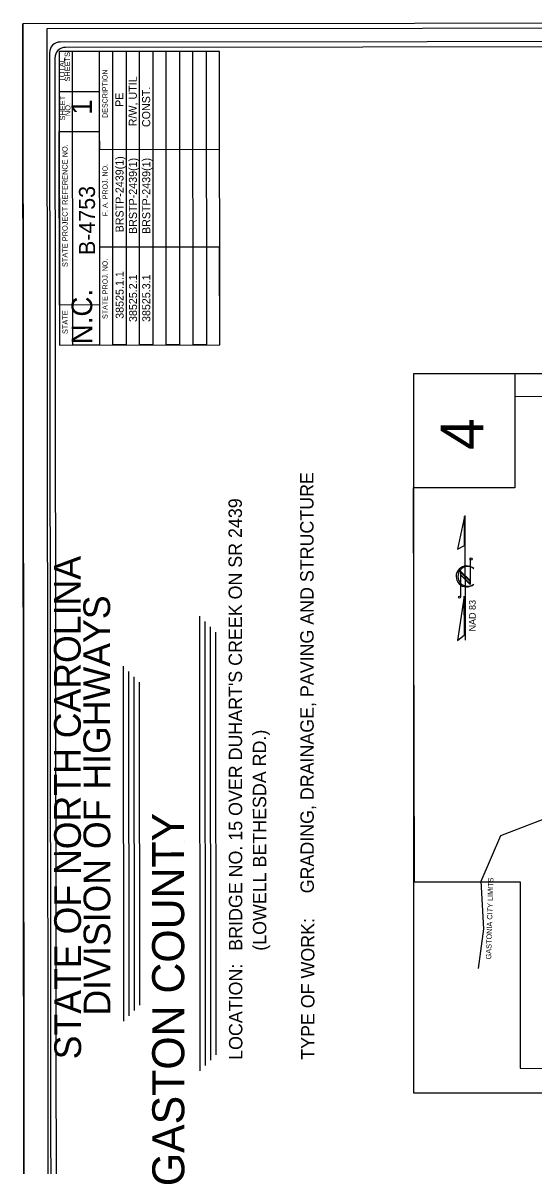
# Model space of a CAD drawing. Extents: x 1372027 to 1374286, y 553832 to 556743.
# Drawn here: x 1373082 to 1373560, y 554446 to 555517 of the extents above; entities that cross this region are included whole.
import ezdxf

# ---------------------------------------------------------------- set-up
doc = ezdxf.new("R2010")
doc.units = 0
for name, color, linetype in [('Default', 7, 'Continuous'), ('Prop Approach Slab', 7, 'Continuous'), ('Prop Approach Slab Hatching', 7, 'Continuous'), ('Prop Dimension Text', 7, 'Continuous'), ('Prop EOT', 7, 'Continuous'), ('Prop North Arrow NAD83 for Plan Sheets CELL', 7, 'Continuous'), ('Prop Roadway Bridge', 7, 'Continuous'), ('Prop Structure Anchor Unit CELL', 7, 'Continuous'), ('Prop Terminator CELL', 7, 'Continuous'), ('Sheet Clip Boundary CELL', 7, 'Continuous'), ('Sheet North Arrow CELL', 7, 'Continuous')]:
    doc.layers.add(name, color=color, linetype=linetype)

msp = doc.modelspace()

# ---------------------------------------------------------------- linework, layer by layer
at = {"layer": 'Prop Approach Slab'}
msp.add_lwpolyline([(1374161.4, 553845.9), (1374159.9, 555512.4), (1373104.8, 555511.5), (1373106.3, 553845)], close=True, dxfattribs=at)
at = {"layer": 'Prop Approach Slab Hatching'}
msp.add_lwpolyline([(1373082.4, 555516), (1373083.9, 553832), (1374183.8, 553833), (1374182.3, 555517)], close=True, dxfattribs=at)
at = {"layer": 'Prop Dimension Text'}
for points in [[(1373448.2, 554513.8), (1373448.2, 555188.2), (1373920.7, 555188.2), (1373920.7, 554513.8)], [(1373448.2, 555081.2), (1373448.2, 555188.2), (1373542.8, 555188.2), (1373542.8, 555081.2)]]:
    msp.add_lwpolyline(points, close=True, dxfattribs=at)
at = {"layer": 'Prop EOT'}
for p, q in [((1373287.5, 554869.5), (1373287.5, 554869.5)), ((1373233.3, 554749.4), (1373233.3, 554749.4))]:
    msp.add_line(p, q, dxfattribs=at)
at = {"layer": 'Prop Roadway Bridge'}
for p, q in [((1373248.4, 554534.9), (1373248, 554960.9)), ((1373253.4, 554539.9), (1373253, 554955.9)), ((1373258.4, 554544.9), (1373258, 554950.9)), ((1373263.4, 554549.9), (1373263, 554945.9)), ((1373176.7, 554581.5), (1373176.4, 554914.2)), ((1373181.7, 554586.5), (1373181.4, 554909.2)), ((1373186.7, 554591.5), (1373186.4, 554904.2)), ((1373191.7, 554596.5), (1373191.4, 554899.2))]:
    msp.add_line(p, q, dxfattribs=at)
for points in [[(1374147.4, 555499.9), (1373117.4, 555499)], [(1373957.4, 555494.8), (1373122.4, 555494)], [(1373107.4, 555489), (1373108.7, 554009)], [(1373112.4, 555484), (1373113.7, 554064)], [(1373266.6, 555215.2), (1373266.4, 555490.2), (1373253.9, 555490.1), (1373254.1, 555215.1), (1373241.6, 555215.1), (1373241.4, 555490.1), (1373228.9, 555490.1), (1373229.1, 555215.1), (1373216.6, 555215.1), (1373216.4, 555490.1), (1373203.9, 555490.1), (1373204.1, 555215.1), (1373191.6, 555215.1), (1373191.4, 555490.1), (1373178.9, 555490.1), (1373179.1, 555215.1), (1373166.6, 555215.1), (1373166.4, 555490.1), (1373153.9, 555490.1), (1373154.1, 555215.1), (1373129.1, 555215), (1373128.9, 555490), (1373116.4, 555490), (1373116.6, 555215), (1373266.6, 555215.2), (1373266.5, 555306.8), (1373154, 555306.7), (1373154.1, 555252.6), (1373116.6, 555252.5), (1373116.4, 555415), (1373153.9, 555415.1), (1373154, 555398.4), (1373266.5, 555398.5), (1373266.4, 555490.2), (1373116.4, 555490), (1373116.4, 555452.5), (1373153.9, 555452.6)]]:
    msp.add_lwpolyline(points, dxfattribs=at)
for centre in [(1373117.3, 555489), (1373122.3, 555484)]:
    msp.add_arc(centre, 10, 90.0509, 180.0509, dxfattribs=at)
at = {"layer": 'Prop Structure Anchor Unit CELL'}
msp.add_line((1373083.9, 553832), (1373082.4, 555516), dxfattribs=at)
at = {"layer": 'Prop Terminator CELL'}
msp.add_lwpolyline([(1373508.7, 554630.8), (1373513.7, 554667.9), (1373511.3, 554712.5), (1373529.7, 554755.2), (1373574.3, 554772.5), (1373580.4, 554781), (1373588.3, 554789.7), (1373590.5, 554804.5), (1373602.7, 554811.3), (1373638.7, 554817.3), (1373686, 554822.7), (1373694.5, 554828.4), (1373707.8, 554832.6), (1373716.8, 554835.6)], dxfattribs=at)
at = {"layer": 'Sheet Clip Boundary CELL'}
msp.add_lwpolyline([(1373920.6, 554536.7), (1373920.1, 555166.7), (1373542.7, 555166.4), (1373542.8, 555081.2), (1373447.6, 555081.1), (1373448.5, 554711.8), (1373547.7, 554711.9), (1373547.8, 554537.3)], close=True, dxfattribs=at)
at = {"layer": 'Sheet North Arrow CELL'}
for p, q in [((1373496.5, 554938.3), (1373496.4, 555055.3)), ((1373500.9, 555014.5), (1373500.9, 554990.5)), ((1373500.9, 554994.3), (1373491.9, 555003.2)), ((1373491.9, 555003.2), (1373492, 554978.8)), ((1373500.9, 554993.4), (1373491.9, 555002.3)), ((1373491.9, 555002.3), (1373491.9, 555000.1)), ((1373500.9, 554991.2), (1373491.9, 555000.1)), ((1373491.9, 555000.1), (1373500.9, 554991.2)), ((1373500.9, 554990.5), (1373491.9, 554999.5)), ((1373504.2, 555005.6), (1373504.3, 555005.5)), ((1373500.9, 554991.2), (1373500.9, 554993.4))]:
    msp.add_line(p, q, dxfattribs=at)
for points in [[(1373495.6, 555054.2), (1373489, 555023.8), (1373495.6, 555027.2)], [(1373495.5, 554979.5), (1373489, 554938.2), (1373495.6, 554943.5)]]:
    msp.add_lwpolyline(points, close=True, dxfattribs=at)
for centre in [(1373501.8, 555014.5), (1373491, 554978.8)]:
    msp.add_circle(centre, 0.954, dxfattribs=at)
for centre, radius, start, end in [((1373497.7, 554998.2), 9.83, 47.891, 312.445), ((1373498.7, 554998.2), 9.21, 53.146, 308.6797)]:
    msp.add_arc(centre, radius, start, end, dxfattribs=at)

# ---------------------------------------------------------------- texts
at = {"layer": 'Default'}
msp.add_text('GASTONIA CITY LIMITS', height=4.95, rotation=88.3665, dxfattribs=at).set_placement((1373520.6, 554639.2))
at = {"layer": 'Prop Dimension Text'}
msp.add_text('4', height=40, rotation=90.0509, dxfattribs=at).set_placement((1373513.3, 555116.7))
at = {"layer": 'Prop North Arrow NAD83 for Plan Sheets CELL'}
for s, height, p in [('R/W, UTIL ', 7.5, (1373189, 555420)), ('PE', 7.5, (1373176.4, 555438.2)), ('CONST.    ', 7.5, (1373201.5, 555419.3)), ('BRSTP-2439(1)', 7.5, (1373176.6, 555320.6)), ('BRSTP-2439(1) ', 7.5, (1373189.1, 555319.1)), ('BRSTP-2439(1) ', 7.5, (1373201.6, 555319.1)), ('B-4753', 15, (1373149.9, 555299.4)), ('38525.1.1', 7.5, (1373176.7, 555239.6)), ('38525.2.1 ', 7.5, (1373189.2, 555236.6)), ('38525.3.1 ', 7.5, (1373201.6, 555236.6)), ('GRADING, DRAINAGE, PAVING AND STRUCTURE ', 12.5, (1373354.7, 554701.2)), ("BRIDGE NO. 15 OVER DUHART'S CREEK ON SR 2439", 12.5, (1373287.7, 554647.4)), ('(LOWELL BETHESDA RD.)                   ', 12.5, (1373310.2, 554647.4)), ('        GASTON COUNTY        ', 30, (1373233.6, 554337.5))]:
    msp.add_text(s, height=height, rotation=90.0509, dxfattribs=at).set_placement(p)
at = {"layer": 'Prop Roadway Bridge'}
for s, height, p in [('TOTAL', 5, (1373121.5, 555461.7)), ('SHEETS', 5, (1373126.5, 555462)), ('DESCRIPTION', 4.8, (1373161.6, 555427.9)), ('SHEET', 5, (1373121.9, 555425.5)), ('NO.', 5, (1373126.9, 555429.6)), ('1', 19.4, (1373147.1, 555430.9)), ('STATE PROJECT REFERENCE NO.', 5, (1373124.3, 555288.1)), ('F. A. PROJ. NO.', 4.8, (1373161.7, 555335.8)), ('STATE PROJ. NO.', 4.8, (1373161.7, 555239.5)), ('N.C.', 19.35, (1373147.3, 555215.8)), ('STATE', 5, (1373124.4, 555225.3)), ('STATE OF NORTH CAROLINA', 25, (1373136.8, 554545.6)), ('DIVISION OF HIGHWAYS', 25, (1373164.3, 554586.6)), ('TYPE OF WORK:', 12.5, (1373355.3, 554545.2)), ('LOCATION: ', 12.5, (1373287.8, 554545.1))]:
    msp.add_text(s, height=height, rotation=90.0509, dxfattribs=at).set_placement(p)
at = {"layer": 'Sheet North Arrow CELL'}
msp.add_text('NAD 83', height=6.3, rotation=90.0509, dxfattribs=at).set_placement((1373506.2, 554946.6))

doc.saveas('drawing.dxf')
